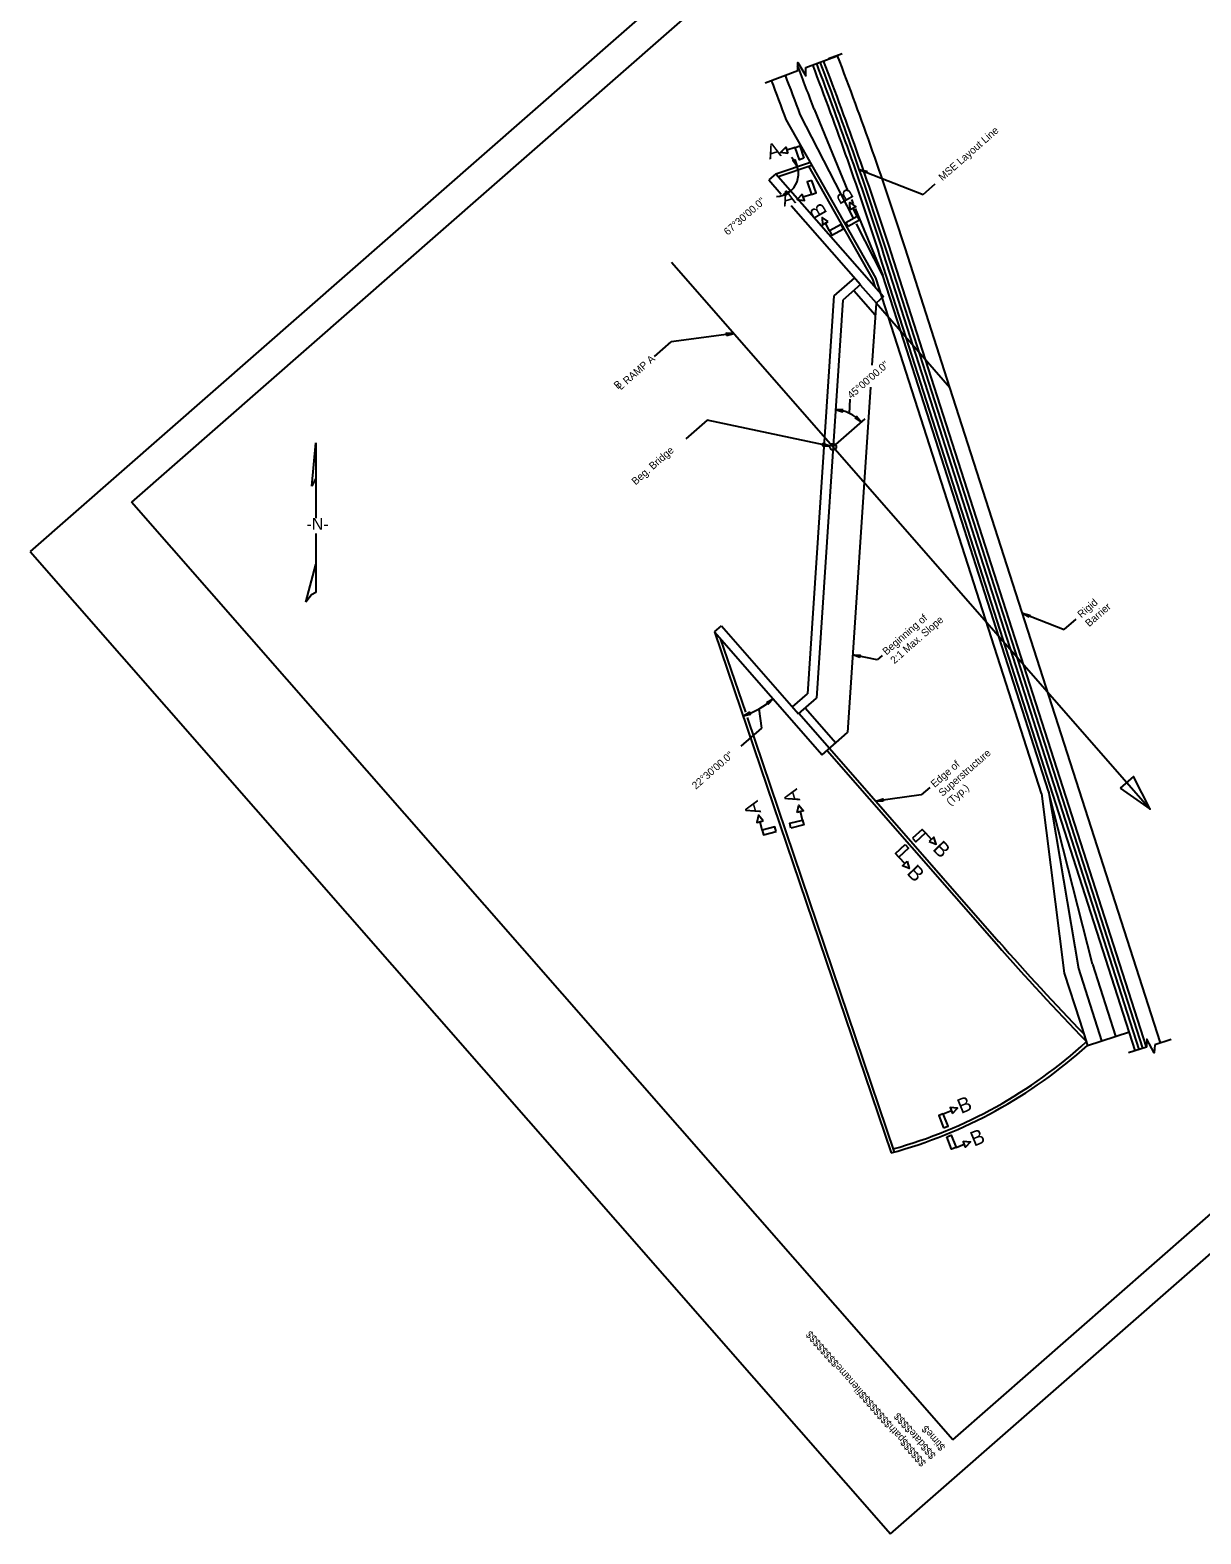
# Model space of a CAD drawing. Extents: x 1970965 to 1971298, y 796258 to 796581.
# Drawn here: x 1970965 to 1971122.8, y 796258.4 to 796461.1 of the extents above; entities that cross this region are included whole.
import ezdxf

# ---------------------------------------------------------------- set-up
doc = ezdxf.new("R2010")
doc.units = 0
for name, color, linetype in [('BR_AUTO DIMENSION', 7, 'Continuous'), ('BR_BORDER LINES', 7, 'Continuous'), ('BR_CENTER LINES', 7, 'Continuous'), ('BR_CONCRETE', 7, 'Continuous'), ('BR_TABLE LINES', 7, 'Continuous'), ('BR_TEXT', 7, 'Continuous'), ('Default', 7, 'Continuous'), ('Level 31', 7, 'Continuous'), ('RD_SHT_ID', 7, 'Continuous')]:
    doc.layers.add(name, color=color, linetype=linetype)

msp = doc.modelspace()

# ---------------------------------------------------------------- linework, layer by layer
at = {"layer": 'BR_AUTO DIMENSION'}
for p, q in [((1971076.76, 796442.29), (1971085.36, 796438.91)), ((1971085.36, 796438.91), (1971086.99, 796440.34)), ((1971049.16, 796417.09), (1971051.4, 796419.05)), ((1971059.84, 796420.19), (1971051.4, 796419.05)), ((1971075.44, 796409.41), (1971075.52, 796411.32)), ((1971073.22, 796404.91), (1971077.53, 796408.68)), ((1971056.25, 796408.5), (1971053.39, 796405.98)), ((1971072.8, 796405), (1971056.25, 796408.5)), ((1971098.77, 796382.47), (1971104.35, 796380.27)), ((1971104.35, 796380.27), (1971105.99, 796381.7)), ((1971079.17, 796376.18), (1971075.87, 796376.88)), ((1971079.84, 796376.77), (1971079.17, 796376.18)), ((1971063.6, 796367), (1971063.24, 796369.59)), ((1971060.83, 796364.57), (1971063.6, 796367)), ((1971085.11, 796358), (1971078.97, 796357.17)), ((1971086.27, 796359.02), (1971085.11, 796358))]:
    msp.add_line(p, q, dxfattribs=at)
for points in [[(1971068.05, 796443.62), (1971068.4, 796442.67), (1971067.79, 796443.48)], [(1971077.64, 796441.78), (1971076.76, 796442.29), (1971077.75, 796442.06)], [(1971066.6, 796438.98), (1971067.52, 796439.4), (1971066.76, 796438.73)], [(1971058.87, 796419.91), (1971059.84, 796420.19), (1971058.83, 796420.2)], [(1971074.56, 796409.9), (1971073.55, 796409.92), (1971074.51, 796409.61)], [(1971076.16, 796408.79), (1971077, 796408.22), (1971076.37, 796409.01)], [(1971071.79, 796405.06), (1971072.8, 796405), (1971071.85, 796405.35)], [(1971099.64, 796381.97), (1971098.77, 796382.47), (1971099.75, 796382.24)], [(1971076.82, 796376.53), (1971075.87, 796376.88), (1971076.88, 796376.82)], [(1971064.28, 796370.45), (1971065.15, 796370.95), (1971064.47, 796370.21)], [(1971062.09, 796368.85), (1971061.11, 796368.62), (1971061.98, 796369.13)], [(1971079.99, 796357.15), (1971078.97, 796357.17), (1971079.94, 796357.45)]]:
    msp.add_lwpolyline(points, close=True, dxfattribs=at)
msp.add_circle((1971073.22, 796404.91), 0.434, dxfattribs=at)
for centre, radius, start, end in [((1971065.51, 796441.69), 3.05, 271.792, 46.7832), ((1971073.22, 796404.91), 5.02, 41.212, 86.212), ((1971057.26, 796379.97), 11.98, 288.712, 311.212)]:
    msp.add_arc(centre, radius, start, end, dxfattribs=at)
at = {"layer": 'BR_BORDER LINES'}
for p, q in [((1971181.27, 796574.92), (1970978.66, 796397.47)), ((1971089.35, 796271.09), (1971291.95, 796448.53)), ((1971089.35, 796271.09), (1970978.66, 796397.47))]:
    msp.add_line(p, q, dxfattribs=at)
at = {"layer": 'BR_CENTER LINES'}
for p, q in [((1971069.53, 796456.01), (1971073.89, 796457.64)), ((1971074.43, 796457.84), (1971072.62, 796457.17)), ((1971064.05, 796453.95), (1971068.45, 796455.6)), ((1971051.44, 796429.77), (1971115.97, 796356.09)), ((1971115.46, 796324), (1971113.03, 796323.26)), ((1971118.8, 796325.03), (1971116.57, 796324.34))]:
    msp.add_line(p, q, dxfattribs=at)
for points in [[(1971068.45, 796455.6), (1971068.45, 796456.7), (1971069.53, 796454.91), (1971069.53, 796456.01)], [(1971116.57, 796324.34), (1971116.5, 796323.25), (1971115.53, 796325.1), (1971115.46, 796324)]]:
    msp.add_lwpolyline(points, dxfattribs=at)
at = {"layer": 'BR_CONCRETE'}
for p, q in [((1971075.92, 796435.8), (1971068.79, 796449.7)), ((1971070.66, 796450.39), (1971075.23, 796439.34)), ((1971078.98, 796427.67), (1971066.91, 796449)), ((1971065.51, 796441.69), (1971070.16, 796443.27)), ((1971065.51, 796441.69), (1971064.57, 796440.87)), ((1971065.51, 796441.69), (1971080.01, 796425.14)), ((1971065.83, 796441.33), (1971070.38, 796442.87)), ((1971078.58, 796427.49), (1971069.95, 796442.73)), ((1971064.57, 796440.87), (1971066.23, 796438.97)), ((1971067.59, 796437.42), (1971076.93, 796426.76)), ((1971075.69, 796438.24), (1971075.93, 796437.66)), ((1971076.2, 796437.02), (1971079.94, 796427.98)), ((1971079.94, 796427.98), (1971076.36, 796434.94)), ((1971114.98, 796323.86), (1971080.55, 796430.96)), ((1971085.67, 796416.69), (1971081.03, 796431.11)), ((1971088.98, 796412.9), (1971082.93, 796431.73)), ((1971083.07, 796419.65), (1971079.54, 796430.64)), ((1971114.5, 796323.71), (1971080.08, 796430.81)), ((1971076.1, 796427.7), (1971073.31, 796425.26)), ((1971078.94, 796426.36), (1971078.58, 796427.49)), ((1971080.69, 796422.37), (1971078.98, 796427.67)), ((1971082.35, 796420.48), (1971079.94, 796427.98)), ((1971073.31, 796425.26), (1971069.76, 796371.64)), ((1971076.93, 796426.76), (1971074.53, 796424.66)), ((1971076.03, 796425.98), (1971078.91, 796422.7)), ((1971076.88, 796426.72), (1971079.01, 796424.29)), ((1971080.01, 796425.14), (1971079.02, 796424.28)), ((1971074.53, 796424.66), (1971070.98, 796371.04)), ((1971079.01, 796424.27), (1971078.46, 796415.9)), ((1971079.01, 796424.29), (1971088.98, 796412.9)), ((1971079.02, 796424.28), (1971079.01, 796424.27)), ((1971101.31, 796358.21), (1971080.69, 796422.37)), ((1971102.26, 796358.51), (1971082.35, 796420.48)), ((1971113.96, 796323.54), (1971083.07, 796419.65)), ((1971115.46, 796324), (1971085.67, 796416.69)), ((1971078.26, 796412.94), (1971075.18, 796366.41)), ((1971117.37, 796324.59), (1971088.98, 796412.9)), ((1971057.26, 796379.97), (1971058.2, 796380.79)), ((1971058.2, 796380.79), (1971068.58, 796368.94)), ((1971057.26, 796379.97), (1971071.76, 796363.42)), ((1971057.26, 796379.97), (1971081.04, 796309.75)), ((1971058.02, 796379.09), (1971061.4, 796369.13)), ((1971067.76, 796369.88), (1971069.76, 796371.64)), ((1971068.58, 796368.94), (1971070.98, 796371.04)), ((1971061.64, 796368.42), (1971081.47, 796309.87)), ((1971068.63, 796368.98), (1971095.57, 796338.22)), ((1971069.47, 796369.72), (1971073.59, 796365.02)), ((1971071.76, 796363.42), (1971075.18, 796366.41)), ((1971072.74, 796364.28), (1971095.57, 796338.22)), ((1971072.41, 796363.99), (1971095.24, 796337.93)), ((1971101.31, 796358.21), (1971104.37, 796333.98)), ((1971102.26, 796358.51), (1971106.28, 796334.59)), ((1971108.18, 796335.2), (1971102.26, 796358.51)), ((1971104.37, 796333.98), (1971106.46, 796327.49)), ((1971106.28, 796334.59), (1971109.41, 796324.85)), ((1971108.18, 796335.2), (1971111.31, 796325.47)), ((1971106.46, 796327.49), (1971107.5, 796324.24)), ((1971107, 796325.8), (1971107.5, 796324.24)), ((1971107.5, 796324.24), (1971113.16, 796326.06))]:
    msp.add_line(p, q, dxfattribs=at)
for centre, radius, start, end in [((1970606.92, 796278.72), 500, 17.8187, 20.9641), ((1970606.92, 796278.72), 494.5, 20.3134, 21.0415), ((1970606.92, 796278.72), 496.44, 17.8187, 20.9672), ((1970606.92, 796278.72), 497, 17.8187, 20.9667), ((1970606.92, 796278.72), 497.5, 17.8187, 20.9662), ((1970606.92, 796278.72), 498, 17.8187, 20.9658), ((1970606.92, 796278.72), 490.5, 20.3134, 20.9724), ((1970606.92, 796278.72), 492.5, 20.3134, 20.9706), ((1971352.19, 796562.97), 341.57, 221.212, 224.1982), ((1971352.19, 796562.97), 341.12, 221.212, 224.0478), ((1971064.02, 796372.25), 64.77, 285.2378, 312.1686), ((1971064.02, 796372.25), 64.33, 285.6088, 312.3472)]:
    msp.add_arc(centre, radius, start, end, dxfattribs=at)
at = {"layer": 'BR_TABLE LINES'}
for p, q in [((1971068.11, 796445.26), (1971066.99, 796444.87)), ((1971070.33, 796438.92), (1971069.21, 796438.53)), ((1971076.49, 796436), (1971075.92, 796437.04)), ((1971072.76, 796434.01), (1971072.19, 796435.05)), ((1971063.67, 796353.24), (1971063.38, 796354.39)), ((1971069.1, 796354.61), (1971068.81, 796355.76)), ((1971085.69, 796352.89), (1971086.49, 796352.01)), ((1971082.09, 796349.63), (1971082.89, 796348.76)), ((1971088.07, 796315.03), (1971089.18, 796315.46)), ((1971089.8, 796310.49), (1971090.9, 796310.92))]:
    msp.add_line(p, q, dxfattribs=at)
for points in [[(1971067.13, 796444.45), (1971066.15, 796444.58), (1971066.84, 796445.29)], [(1971069.3, 796443.79), (1971068.69, 796443.58), (1971068.11, 796445.26), (1971068.72, 796445.47)], [(1971070.37, 796440.81), (1971069.75, 796440.6), (1971070.33, 796438.92), (1971070.95, 796439.13)], [(1971069.07, 796438.95), (1971068.37, 796438.24), (1971069.36, 796438.11)], [(1971075.53, 796436.83), (1971075.49, 796437.82), (1971076.31, 796437.25)], [(1971072.58, 796435.26), (1971071.76, 796435.83), (1971071.8, 796434.83)], [(1971075.25, 796434.58), (1971074.93, 796435.15), (1971076.49, 796436), (1971076.8, 796435.43)], [(1971074.63, 796434.29), (1971074.32, 796434.86), (1971072.76, 796434.01), (1971073.07, 796433.44)], [(1971068.38, 796355.65), (1971068.59, 796356.62), (1971069.24, 796355.87)], [(1971063.81, 796354.5), (1971063.15, 796355.25), (1971062.95, 796354.28)], [(1971067.55, 796353.54), (1971067.38, 796354.17), (1971069.1, 796354.61), (1971069.27, 796353.98)], [(1971065.55, 796353.06), (1971065.39, 796353.69), (1971063.67, 796353.24), (1971063.83, 796352.61)], [(1971083.94, 796352.16), (1971084.38, 796351.68), (1971085.69, 796352.89), (1971085.25, 796353.36)], [(1971086.17, 796351.71), (1971087.1, 796351.36), (1971086.82, 796352.32)], [(1971082.95, 796351.31), (1971083.39, 796350.83), (1971082.09, 796349.63), (1971081.64, 796350.11)], [(1971083.22, 796349.06), (1971083.49, 796348.1), (1971082.56, 796348.46)], [(1971089.34, 796315.05), (1971090.01, 796315.78), (1971089.02, 796315.87)], [(1971088.11, 796313.14), (1971088.72, 796313.37), (1971088.07, 796315.03), (1971087.47, 796314.79)], [(1971088.54, 796311.91), (1971089.15, 796312.14), (1971089.8, 796310.49), (1971089.19, 796310.25)], [(1971090.74, 796311.33), (1971091.73, 796311.24), (1971091.06, 796310.51)]]:
    msp.add_lwpolyline(points, close=True, dxfattribs=at)
at = {"layer": 'BR_TEXT'}
for p, q in [((1971002.96, 796399.61), (1971003.5, 796405.43)), ((1971003.5, 796405.43), (1971003.5, 796395.31)), ((1971003.5, 796405.43), (1971003.5, 796400.69)), ((1971003.5, 796400.69), (1971002.96, 796399.61)), ((1971003.5, 796393.22), (1971003.5, 796385.27)), ((1971002.18, 796383.99), (1971003.5, 796389.07)), ((1971003.5, 796389.07), (1971003.5, 796388.44)), ((1971003.5, 796388.44), (1971003.5, 796385.27))]:
    msp.add_line(p, q, dxfattribs=at)
msp.add_lwpolyline([(1971003.5, 796385.27), (1971002.93, 796384.96), (1971002.18, 796383.99)], dxfattribs=at)
at = {"layer": 'Default'}
msp.add_lwpolyline([(1971111.91, 796358.91), (1971115.97, 796356.09), (1971113.71, 796360.49)], close=True, dxfattribs=at)
at = {"layer": 'Level 31'}
for p, q in [((1971181.65, 796580.56), (1970964.99, 796390.82)), ((1971080.95, 796258.42), (1971297.6, 796448.16)), ((1970964.99, 796390.82), (1971080.95, 796258.42))]:
    msp.add_line(p, q, dxfattribs=at)

# ---------------------------------------------------------------- texts
at = {"layer": 'BR_TEXT'}
for s, height, rotation, p in [('MSE Layout Line', 0.9998, 41.212, (1971087.97, 796440.69)), ('A', 2, 17.1701, (1971064.63, 796443.61)), ('A', 2, 17.1701, (1971066.59, 796437.26)), ('B', 2, 119.9675, (1971076.09, 796438.4)), ('67%%D30\'00.0"', 0.9998, 41.212, (1971059.03, 796433.34)), ('B', 2, 119.9675, (1971072.49, 796436.4)), ('L RAMP A', 1, 41.212, (1971044.61, 796412.51)), ('45%%D00\'00.0"', 0.9998, 41.212, (1971075.68, 796411.31)), ('B', 1, 41.212, (1971044.2, 796412.63)), ('Beg. Bridge', 0.9998, 41.212, (1971046.6, 796399.7)), ('-N-', 1.6, 360, (1971002.25, 796393.72)), ('Rigid', 1, 41.212, (1971106.69, 796381.78)), ('Beginning of', 1, 41.212, (1971080.42, 796376.79)), ('Barrier', 1, 41.212, (1971107.74, 796380.58)), ('2:1 Max. Slope', 1, 41.212, (1971081.48, 796375.59)), ('Superstructure', 1, 41.212, (1971087.97, 796357.73)), ('22%%D30\'00.0"', 0.9998, 41.212, (1971054.73, 796358.69)), ('Edge of', 1, 41.212, (1971086.92, 796358.93)), ('A', 2, 106.3721, (1971068.83, 796357.25)), ('(Typ.)', 1, 41.212, (1971089.02, 796356.52)), ('A', 2, 106.3721, (1971063.54, 796355.65)), ('B', 2, 313.8682, (1971086.53, 796350.63)), ('B', 2, 313.8682, (1971083.05, 796347.4)), ('B', 2, 22.5518, (1971090.48, 796314.99)), ('B', 2, 22.5518, (1971092.23, 796310.58))]:
    msp.add_text(s, height=height, rotation=rotation, dxfattribs=at).set_placement(p)
at = {"layer": 'RD_SHT_ID'}
for s, height, p in [('$$$$$$path$$$$$$$$filename$$$$$$$$', 0.9877, (1971085.83, 796268.01)), ('$$$date$$$$', 0.9877, (1971087.14, 796269.02)), ('$time$', 0.988, (1971088.41, 796270.13))]:
    msp.add_text(s, height=height, rotation=131.212, dxfattribs=at).set_placement(p)

doc.saveas('drawing.dxf')
